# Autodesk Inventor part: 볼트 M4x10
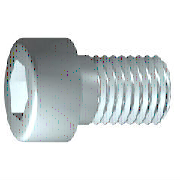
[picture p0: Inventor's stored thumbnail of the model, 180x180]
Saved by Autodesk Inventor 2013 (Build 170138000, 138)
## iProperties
IsCustomPart: 1
Created: 2012-02
Part Number: 볼트 M4x10
Material: 스테인리스강
Description: 6각 소켓 머리 캡 나사
Document SubType Name: Modeling
Standard: ISO 4762
Designer: mduedu
Standard Revision: Fourth edition 2004-03-01
Standards Organization: ISO
Language: ko-KR
Size Designation: M4 x 10
Categories: <MemberInstance><Categories><Category DisplayName="조임쇠" InternalName="e4da775c-781d-43d5-af7c-5136215cf5a6" Mnemonic="FSTN"><Category DisplayName="볼트" InternalN
Density: 8.08 g/cm^3
Mass: 2.0939 g
Surface Area: 3.06255 cm^2
Volume: 0.259146 cm^3
Author: mduedu
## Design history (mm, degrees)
sketch "스케치1"
  geometry: L1 (-1, 0)-(10, 0); L2 (10, 0)-(10, 2); L3 (10, 2)-(1.75, 2); L4 (1.75, 2)-(1.32, 2); L5 (1.32, 2)-(0, 2); L6 (0, 2)-(0, 3.5); L7 (0, 3.5)-(-4, 3.5); L8 (-4, 3.5)-(-4, 1.732); L9 (-4, 1.732)-(-2, 1.732); L10 (-2, 1.732)-(-1, 0); L11 (-6.8, 0)-(12.8, 0) reference; L12 (0, -0.7)-(0, 4.2) reference; L13 (1.75, 2)-(0, 2)
  constraints: 22 end point, 6 parallel, 2 collinear, 2 perpendicular, 1 horizontal, 1 point on line
  dimensions: "d1" = 8.25 distance from line of L3.end L2 (= GEL); "d2" = 0.42952 distance of L4.end L3.end (computed from GAL); "d3" = 4 distance between parallel lines of L8 L6 (= KOH); "d4" = 2 distance of L8.end L9.end (= INTI); "d5" = 60 deg angle of L10 L1; "d6" = 4 diameter of L3 L1 (= GD); "d7" = 4 diameter of L5 L1 (= BDM); "d8" = 3.4641 diameter of L9 L1 (= 1.1547 x SW); "d9" = 7 diameter of L7 L1 (= KOD); "d26" = 10 distance between parallel lines of L12 L2 (= NLG)
revolve "본체" sketch "스케치1" stored, may be unused: angle "d10" = 90 deg
sketch "스케치2"
  geometry: L1 (0, -4.9)-(0, 4.9) reference; L2 (-4.9, 0)-(4.9, 0) reference; L3 (1.732, 0)-(0.866, -1.5); L4 (0.866, -1.5)-(-0.866, -1.5); L5 (-0.866, -1.5)-(-1.732, 0); L6 (-1.732, 0)-(-0.866, 1.5); L7 (-0.866, 1.5)-(0.866, 1.5); L8 (0.866, 1.5)-(1.732, 0); 2 further points
  constraints: 12 end point, 1 coincident, 1 horizontal alignment, 1 point on line, 12 other
extrude "슬롯" join sketch "스케치2" stored distance "d11" = 10; taper "d12" = 0 deg
workplane "Work Plane1"
body "Solid1"
fillet "모깎기1" dims "d17" = 0.4 (= RR)
feature "스레드" dims "d13" = 8.25 (= GEL), "d14" = 0
chamfer "모따기1" distance "d15" = 0.42941 (= -0.5 x SPD + 0.5 x GD); stored, may be unused: second distance "d16" = 0.42941 (= GUL), angle "d27" = 45 deg
other parameters: "GD" = 4 [user parameter; used in 2 equation terms], "NLG" = 10 [user parameter; used in 1 equation term], "GEL" = 8.25 [user parameter; used in 2 equation terms], "KOD" = 7 [user parameter; used in 1 equation term], "KOH" = 4 [user parameter; used in 1 equation term], "INTI" = 2 [user parameter; used in 1 equation term], "GAL" = 0.42941 (= 0.61345 x PTC) [user parameter; used in 1 equation term], "GUL" = 0.42941 (= 0.61345 x PTC) [user parameter; used in 1 equation term], "BDM" = 4 (= NND) [user parameter; used in 1 equation term], "SW" = 3 [user parameter; used in 2 equation terms], "RR" = 0.4 [user parameter; used in 1 equation term], "SPD" = 3.14117 (= NND - 1.2269 x PTC) [user parameter; used in 1 equation term], "d19" = 0, "d28" = 0, "d29" = 0, "R" = 0.1 [user parameter], "TOA" = 30 deg [user parameter], "GD1" = 3.14117 (= THREADDIA - 1.2269 x PTC) [user parameter], "THREADDIA" = 4 [user parameter; used in 1 equation term], "FAWI" = 45 deg [user parameter], "TPU" = 14.28571 (computed from PTC) [user parameter], "PTC" = 0.7 [user parameter; used in 5 equation terms], "NND" = 4 [user parameter; used in 2 equation terms], "E0" = 3.465 (= 1.155 x SW) [user parameter]
